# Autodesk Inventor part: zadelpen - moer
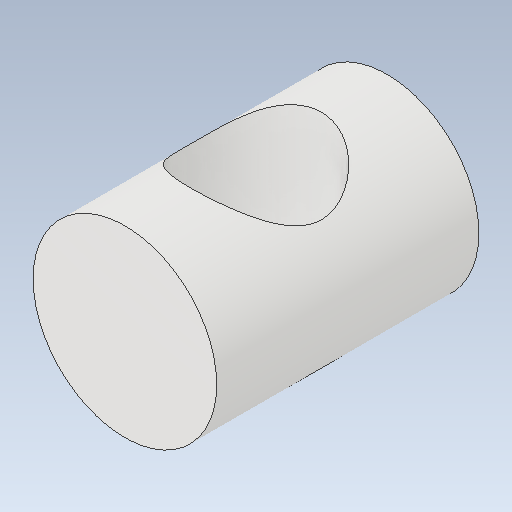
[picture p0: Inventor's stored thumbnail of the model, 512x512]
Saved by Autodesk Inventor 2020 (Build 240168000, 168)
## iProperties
Created: 2017-11
Part Number: zadelpen - moer
Material: Ogólny
Document SubType Name: Modeling
Designer: Tomasz
Density: 1 g/cm^3
Appearance: Domyślna
Author: Tomasz
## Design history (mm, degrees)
feature "Solid1"
node "Bryła1"
